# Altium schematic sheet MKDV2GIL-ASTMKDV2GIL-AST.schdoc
size 127 x 101 mm
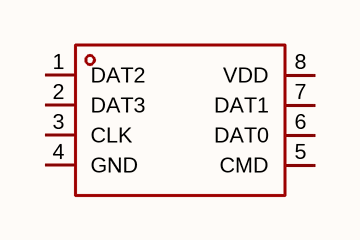
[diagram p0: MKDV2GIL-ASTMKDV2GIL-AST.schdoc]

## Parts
U?  mkdv2gil-ast  [LGA-8_L6.0-W8.0-P1.27-TL]  (value not drawn)

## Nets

Not connected (* = marked no-connect by the designer): U? 1(DAT2) 2(DAT3) 3(CLK) 4(GND) 5(CMD) 6(DAT0) 7(DAT1) 8(VDD)

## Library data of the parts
U? = mkdv2gil-ast: 存储容量:2Gbit;时钟频率(fc):50MHz;工作电压:2.7V~3.6V;; Manufacturer: MK(米客方德); AddInBom: yes; ModelId: 1f88d973af574684b0007f41a35ee8d9; ModelName: LGA-8_L6.0-W8.0-H0.8-P1.27; ModelTransform: 314.96,236.22,0,0,0,0,0,0.005,0; Memory Size: 2Gbit; Clock Frequency: 50MHz; Interface: SD2.0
